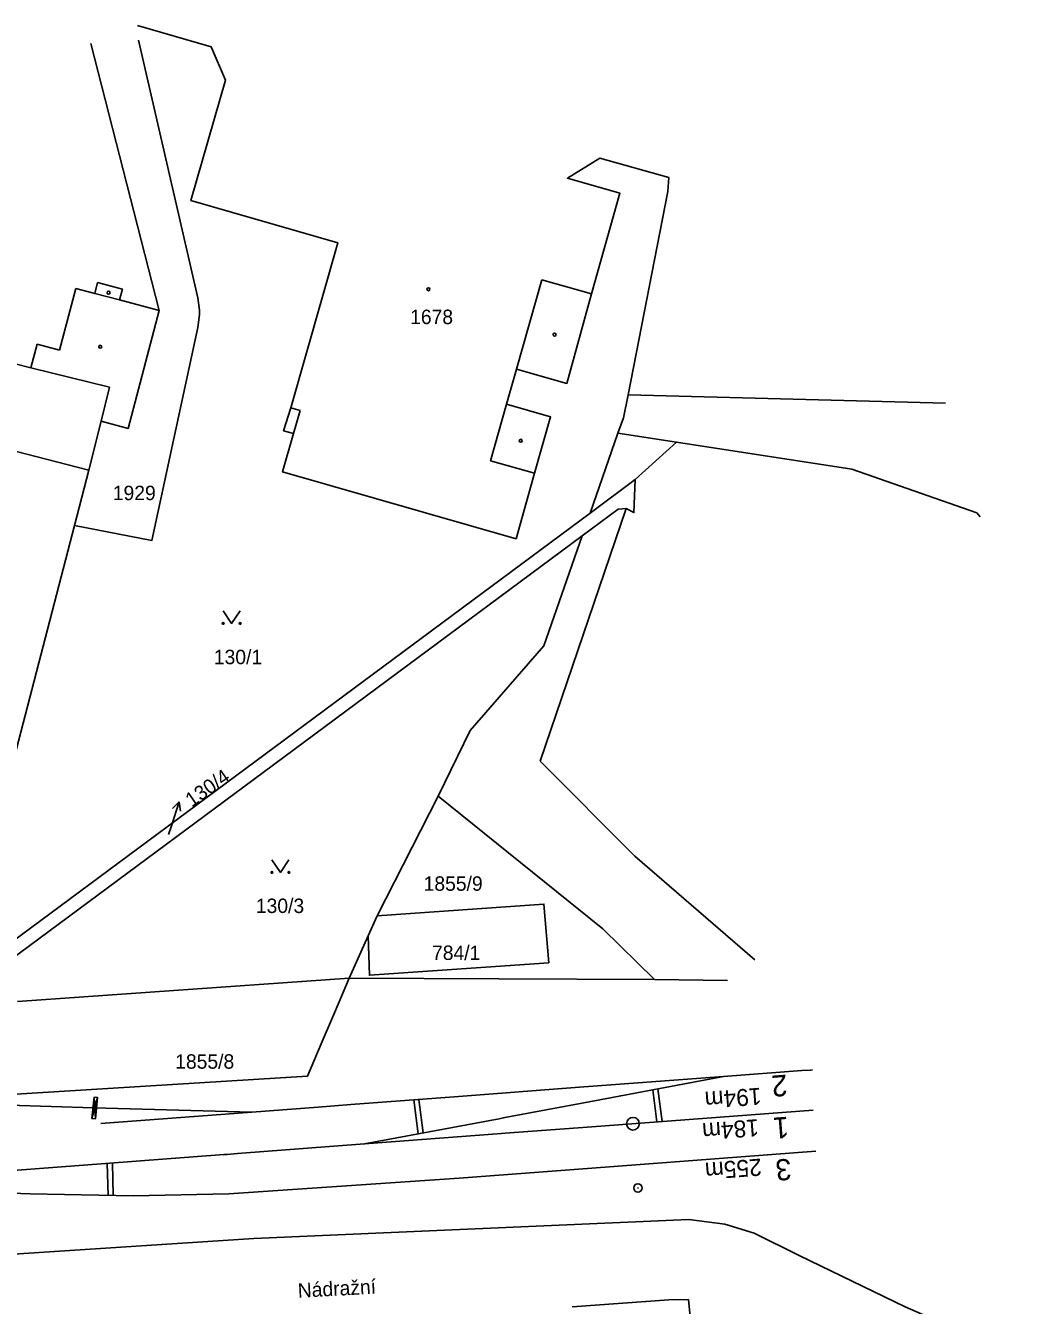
# Model space of a CAD drawing. Extents: x -779330 to -774454, y -1144748 to -1142831.
# Drawn here: x -774787.8 to -774670.6, y -1144444.3 to -1144293.5 of the extents above; entities that cross this region are included whole.
import ezdxf

# ---------------------------------------------------------------- set-up
doc = ezdxf.new("R2010")
doc.units = 0
for name, color, linetype in [('Hranice parcel', 7, 'Continuous'), ('Parcelní čísla', 7, 'Continuous'), ('Pop  PČ popisy', 7, 'Continuous'), ('Vnitřní kresba', 7, 'Continuous'), ('Vrstva 1', 7, 'Continuous'), ('Vrstva 7', 7, 'Continuous'), ('Značky budov', 7, 'Continuous'), ('Značky kultur', 7, 'Continuous')]:
    doc.layers.add(name, color=color, linetype=linetype)

msp = doc.modelspace()

# ---------------------------------------------------------------- linework, layer by layer
at = {"layer": 'Hranice parcel'}
for p, q in [((-774716.78, -1144337.02), (-774679.41, -1144338.01)), ((-774721.28, -1144350.96), (-774718.02, -1144341.55)), ((-774782, -1144352.41), (-774780.31, -1144345.89)), ((-774746.37, -1144398.39), (-774739.17, -1144384.29)), ((-774746.37, -1144398.39), (-774747.42, -1144400.74)), ((-774749.65, -1144405.72), (-774747.42, -1144400.74)), ((-774788.71, -1144408.47), (-774749.65, -1144405.72)), ((-774713.68, -1144405.89), (-774705.08, -1144406))]:
    msp.add_line(p, q, dxfattribs=at)
for points in [[(-774774.57, -1144293.53), (-774765.9, -1144296.02), (-774764.22, -1144299.97), (-774768.29, -1144314.14), (-774750.98, -1144319.11), (-774756.51, -1144338.56), (-774757.38, -1144341.25), (-774756.2, -1144341.59), (-774757.5, -1144346.11), (-774730, -1144353.97), (-774727.82, -1144346.25), (-774725.92, -1144339.62), (-774731.12, -1144338.14), (-774729.94, -1144333.99), (-774724.02, -1144335.67), (-774721.09, -1144325.13), (-774717.77, -1144313.27), (-774723.95, -1144311.51), (-774720.12, -1144309.16), (-774712, -1144311.41)], [(-774774.48, -1144295.25), (-774767.47, -1144325.61), (-774767.27, -1144327.04), (-774767.26, -1144327.55), (-774767.48, -1144329.1), (-774772.89, -1144354.17), (-774782, -1144352.41)], [(-774780.31, -1144345.89), (-774778.87, -1144340.14), (-774775.69, -1144340.97), (-774772.03, -1144327.08), (-774780.09, -1144295.65)], [(-774716.78, -1144337.02), (-774712.11, -1144313.08), (-774712, -1144311.41)], [(-774824.66, -1144334.51), (-774820.92, -1144335.47), (-774798.77, -1144341.16), (-774780.31, -1144345.89)], [(-774718.02, -1144341.55), (-774717.33, -1144339.74), (-774716.78, -1144337.02)], [(-774718.02, -1144341.55), (-774711.1, -1144342.61), (-774690.44, -1144345.78), (-774675.74, -1144350.91), (-774675.34, -1144351.41)], [(-774722.22, -1144353.64), (-774717.98, -1144350.5), (-774717.01, -1144350.41), (-774716.11, -1144350.89), (-774715.95, -1144347), (-774721.28, -1144350.96)], [(-774801.98, -1144406.47), (-774799.57, -1144406.26), (-774796.3, -1144405.69), (-774793.89, -1144404.6), (-774791.79, -1144403.24), (-774759.55, -1144379.36), (-774721.28, -1144350.96)], [(-774722.22, -1144353.64), (-774758.58, -1144380.6), (-774790.75, -1144404.47), (-774793.02, -1144405.95), (-774795.8, -1144407.18), (-774799.56, -1144407.9), (-774820.31, -1144409.63), (-774822.18, -1144410.3), (-774823.4, -1144411.16), (-774824.38, -1144412.31), (-774825.86, -1144415.63)], [(-774804.69, -1144399.57), (-774793.9, -1144398.06), (-774782, -1144352.41)], [(-774739.17, -1144384.29), (-774735.41, -1144376.57), (-774726.72, -1144366.58), (-774722.22, -1144353.64)], [(-774739.17, -1144384.29), (-774719.77, -1144399.93), (-774713.68, -1144405.89)], [(-774747.42, -1144400.74), (-774747.27, -1144405.4), (-774726.15, -1144403.92), (-774726.72, -1144397.01), (-774746.37, -1144398.39)], [(-774749.65, -1144405.72), (-774750.72, -1144408.24), (-774751.62, -1144410.36), (-774752.94, -1144413.48), (-774754.55, -1144417.27), (-774825.82, -1144421.69), (-774826.54, -1144421.73)], [(-774713.68, -1144405.89), (-774732.03, -1144405.8), (-774749.65, -1144405.72)], [(-774454, -1144408.27), (-774492.93, -1144411.59), (-774550.57, -1144426.11), (-774550.13, -1144433.51), (-774643.48, -1144453.01), (-774648.56, -1144453.29), (-774652.59, -1144453.21), (-774659.68, -1144452.39), (-774671.53, -1144449.5), (-774677.59, -1144447.3), (-774684.17, -1144444.45), (-774696.63, -1144438.42), (-774701.94, -1144435.76), (-774705.42, -1144434.73), (-774709.64, -1144434.17), (-774760.86, -1144436.38), (-774828.33, -1144440.79), (-774828.91, -1144435.35), (-774832.04, -1144435.58)], [(-774707.39, -1144466.87), (-774709.7, -1144443.6), (-774712, -1144443.61), (-774723.37, -1144444.44)]]:
    msp.add_lwpolyline(points, dxfattribs=at)
at = {"layer": 'Pop  PČ popisy'}
for p, q in [((-774770.59, -1144387.81), (-774769.66, -1144384.96)), ((-774769.66, -1144384.96), (-774770.45, -1144385.75)), ((-774769.66, -1144384.96), (-774769.5, -1144386.06)), ((-774770.92, -1144388.83), (-774770.59, -1144387.81))]:
    msp.add_line(p, q, dxfattribs=at)
at = {"layer": 'Vnitřní kresba'}
for p, q in [((-774726.96, -1144323.49), (-774729.94, -1144333.99)), ((-774721.09, -1144325.13), (-774726.96, -1144323.49)), ((-774783.77, -1144331.76), (-774781.84, -1144324.48)), ((-774781.84, -1144324.48), (-774779.61, -1144325.07)), ((-774779.61, -1144325.07), (-774779.28, -1144323.81)), ((-774779.61, -1144325.07), (-774776.7, -1144325.84)), ((-774779.28, -1144323.81), (-774776.36, -1144324.58)), ((-774776.36, -1144324.58), (-774776.7, -1144325.84)), ((-774776.7, -1144325.84), (-774772.03, -1144327.08)), ((-774787.13, -1144333.84), (-774786.4, -1144331.07)), ((-774786.4, -1144331.07), (-774783.77, -1144331.76)), ((-774796.31, -1144331.56), (-774787.13, -1144333.84)), ((-774787.13, -1144333.84), (-774777.87, -1144336.13)), ((-774777.87, -1144336.13), (-774778.87, -1144340.14)), ((-774755.42, -1144338.87), (-774756.51, -1144338.56)), ((-774731.12, -1144338.14), (-774733, -1144344.78)), ((-774756.2, -1144341.59), (-774755.42, -1144338.87)), ((-774715.95, -1144347), (-774711.1, -1144342.61)), ((-774733, -1144344.78), (-774727.82, -1144346.25)), ((-774717.01, -1144350.41), (-774727.14, -1144380.18)), ((-774727.14, -1144380.18), (-774715.99, -1144391.37)), ((-774715.99, -1144391.37), (-774701.89, -1144403.58))]:
    msp.add_line(p, q, dxfattribs=at)
at = {"layer": 'Vrstva 1'}
for points in [[(-774695.09, -1144416.54), (-774695.33, -1144416.56), (-774696.34, -1144416.63), (-774705.58, -1144417.32), (-774721.39, -1144420.3), (-774731.5, -1144422.2), (-774731.98, -1144422.29), (-774747.83, -1144425.26), (-774762.82, -1144426.39), (-774764.03, -1144426.49), (-774764.4, -1144426.51)], [(-774695.09, -1144416.54), (-774695.33, -1144416.56), (-774696.34, -1144416.63), (-774705.58, -1144417.32), (-774722, -1144418.55), (-774737.29, -1144419.71), (-774749.44, -1144420.63)], [(-774779.78, -1144421), (-774804.73, -1144420.22), (-774818.9, -1144419.64), (-774827.35, -1144419), (-774829.24, -1144418.79)], [(-774749.44, -1144420.63), (-774753.32, -1144420.92), (-774761.11, -1144421.51), (-774779.78, -1144421)], [(-774749.44, -1144420.63), (-774753.32, -1144420.92), (-774761.11, -1144421.51), (-774778.91, -1144422.85)], [(-774695.01, -1144421.28), (-774721.06, -1144423.24), (-774731.26, -1144424.01), (-774731.71, -1144424.05), (-774747.83, -1144425.26), (-774762.82, -1144426.39), (-774764.03, -1144426.49), (-774764.4, -1144426.51)], [(-774694.69, -1144426.13), (-774721.06, -1144428.11), (-774736.69, -1144429.29), (-774763.81, -1144431.14), (-774775.1, -1144431.37), (-774787.23, -1144431.13), (-774796.99, -1144430.79), (-774797.44, -1144430.78), (-774813.59, -1144430.23), (-774828.58, -1144431.36), (-774829.12, -1144431.4), (-774830.16, -1144431.48)], [(-774764.4, -1144426.51), (-774781.47, -1144427.81), (-774797.03, -1144428.98), (-774797.52, -1144429.01), (-774813.59, -1144430.23), (-774828.58, -1144431.36), (-774829.12, -1144431.4), (-774830.16, -1144431.48)]]:
    msp.add_lwpolyline(points, dxfattribs=at)
at = {"layer": 'Vrstva 7'}
for p, q in [((-774779.29, -1144419.81), (-774779.94, -1144422.26)), ((-774741.52, -1144424.08), (-774742.05, -1144420.07)), ((-774740.93, -1144423.97), (-774741.45, -1144420.02)), ((-774713.4, -1144422.66), (-774713.9, -1144418.89)), ((-774712.8, -1144422.62), (-774713.31, -1144418.78)), ((-774713.36, -1144420.69), (-774713.36, -1144420.69)), ((-774741.51, -1144421.91), (-774741.51, -1144421.91)), ((-774778.03, -1144431.31), (-774778.14, -1144427.55)), ((-774777.43, -1144431.32), (-774777.54, -1144427.51)), ((-774777.79, -1144429.45), (-774777.79, -1144429.45)), ((-774715.59, -1144430.45), (-774715.69, -1144430.46))]:
    msp.add_line(p, q, dxfattribs=at)
msp.add_lwpolyline([(-774779.54, -1144422.3), (-774779.69, -1144419.77), (-774779.29, -1144419.81), (-774779.54, -1144422.3), (-774779.94, -1144422.26), (-774779.69, -1144419.77)], dxfattribs=at)
for centre, radius in [((-774716.23, -1144422.88), 0.75), ((-774715.64, -1144430.45), 0.5)]:
    msp.add_circle(centre, radius, dxfattribs=at)
at = {"layer": 'Značky budov'}
for centre in [(-774777.99, -1144324.99), (-774740.31, -1144324.58), (-774778.97, -1144331.36), (-774725.46, -1144329.93), (-774729.44, -1144342.43)]:
    msp.add_circle(centre, 0.175, dxfattribs=at)
at = {"layer": 'Značky kultur'}
for points in [[(-774764.49, -1144362.45), (-774763.49, -1144363.95), (-774762.49, -1144362.45)], [(-774758.75, -1144391.78), (-774757.75, -1144393.28), (-774756.75, -1144391.78)]]:
    msp.add_lwpolyline(points, dxfattribs=at)
for centre in [(-774764.49, -1144363.95), (-774762.49, -1144363.95), (-774758.75, -1144393.28), (-774756.75, -1144393.28)]:
    msp.add_circle(centre, 0.1, dxfattribs=at)

# ---------------------------------------------------------------- texts
at = {"layer": 'Parcelní čísla'}
for s, p in [('1678', (-774742.47, -1144328.69)), ('1929', (-774777.49, -1144349.43)), ('130/1', (-774765.59, -1144368.75)), ('1855/9', (-774740.88, -1144395.44)), ('130/3', (-774760.64, -1144398.06)), ('784/1', (-774739.89, -1144403.59)), ('1855/8', (-774770.14, -1144416.4))]:
    msp.add_text(s, height=1.7, dxfattribs=at).set_placement(p)
msp.add_text('130/4', height=1.7, rotation=35, dxfattribs=at).set_placement((-774768.19, -1144385.65))
at = {"layer": 'Pop  PČ popisy'}
msp.add_text('Nádražní', height=1.7, rotation=3, dxfattribs=at).set_placement((-774755.66, -1144443.38))
at = {"layer": 'Vrstva 1'}
for s, height, rotation, p in [('2', 2.5, 184.281, (-774698.13, -1144417.09)), ('194m', 2, 184.281, (-774701.17, -1144418.63)), ('184m', 2, 184.3144, (-774701.47, -1144422.33)), ('1', 2.5, 184.3144, (-774697.94, -1144422.04)), ('255m', 2, 184.3038, (-774701.14, -1144426.98)), ('3', 2.5, 184.3038, (-774697.66, -1144426.98))]:
    msp.add_text(s, height=height, rotation=rotation, dxfattribs=at).set_placement(p)

doc.saveas('drawing.dxf')
